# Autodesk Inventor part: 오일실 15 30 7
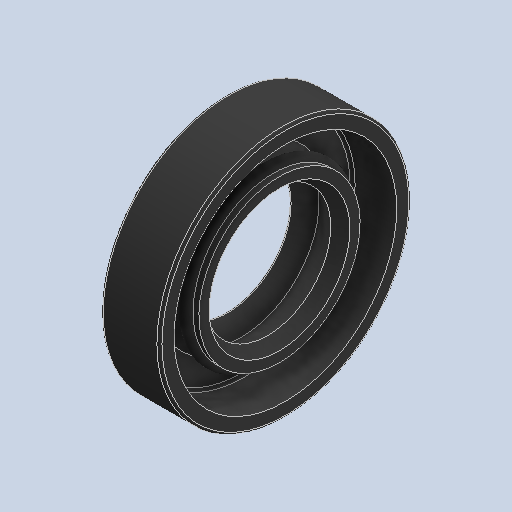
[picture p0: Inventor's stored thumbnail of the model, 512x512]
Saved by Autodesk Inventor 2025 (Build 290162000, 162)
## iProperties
Created: 2024-07
Part Number: 오일실 15 30 7
Material: 고무
Description: 오일-실
Document SubType Name: Modeling
Designer: Administrator
Density: 0.93 g/cm^3
Appearance: 기본값
Author: jhkim
Sending System: Autodesk Inventor 2025
Preprocessor: ST-DEVELOPER v20
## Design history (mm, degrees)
feature "Solid1"
node "솔리드1"
